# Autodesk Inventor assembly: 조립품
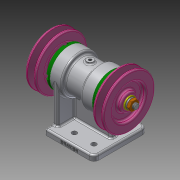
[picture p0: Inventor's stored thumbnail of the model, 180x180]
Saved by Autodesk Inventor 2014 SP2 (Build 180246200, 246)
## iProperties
Created: 2020-06
Part Number: 조립품
Document SubType Name: Assembly
Designer: Administrator
Author: Administrator
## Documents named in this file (12)
- C:\Users\Administrator\Desktop\700606V1043\조립품.iam
- C:\Users\Administrator\Desktop\700606V1043\본체.ipt
- C:\Users\Administrator\Desktop\700606V1043\베어링 6204.ipt
- C:\Users\Administrator\Desktop\700606V1043\축.ipt
- C:\Users\Administrator\Desktop\700606V1043\커버.ipt
- C:\Users\Administrator\Desktop\700606V1043\오일 실 20 32 5.ipt
- C:\Users\Administrator\Desktop\700606V1043\키 5x5x12.ipt
- C:\Users\Administrator\Desktop\700606V1043\V-벨트풀리.ipt
- C:\Users\Administrator\Desktop\700606V1043\평면 와셔 10x21.ipt
- C:\Users\Administrator\Desktop\700606V1043\스프링 와셔 10.ipt
- C:\Users\Administrator\Desktop\700606V1043\너트 M10.ipt
- C:\Users\Administrator\Desktop\700606V1043\볼트 M4.ipt
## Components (2 placed, 1 different names)
1. V-벨트풀리:1 — 각도:3
2. V-벨트풀리:2 — 각도:4
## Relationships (2: Angle 2)
- 각도:3 [Angle]: V-벨트풀리:1
- 각도:4 [Angle]: V-벨트풀리:2
